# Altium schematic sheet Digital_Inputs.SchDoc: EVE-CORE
size A4; Organization: Ingenia Motion Control; Address1: Carrer Avila, 124, 2B; Address2: 08018 Barcelona Spain; Address3: www.ingeniamc.com; Address4: www.ingeniamc.com; Documentation: https://doc.ingeniamc.com/x/coAZBg
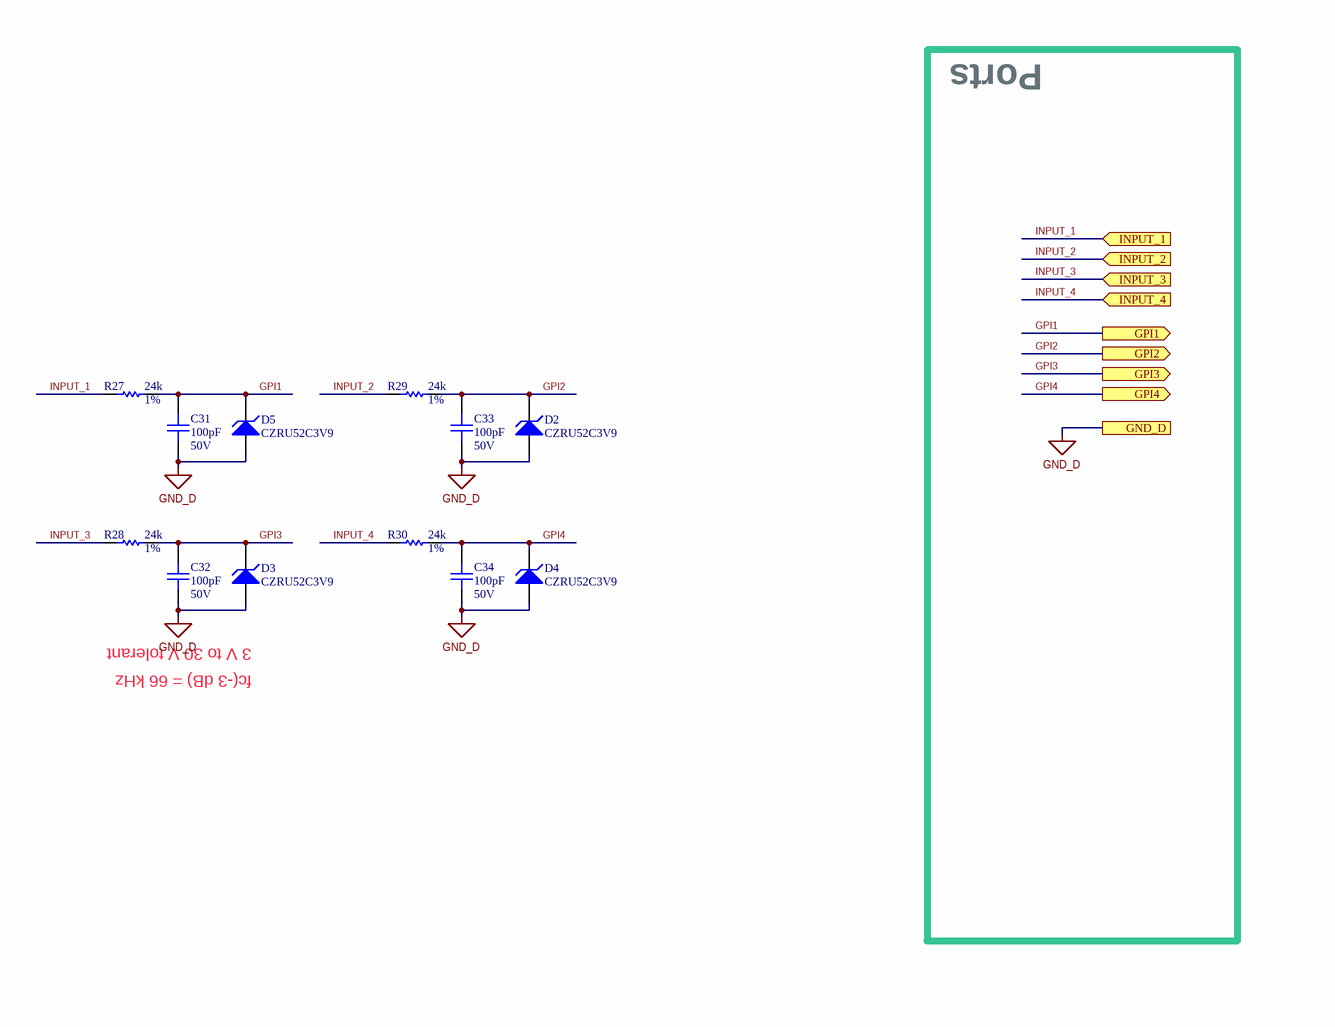
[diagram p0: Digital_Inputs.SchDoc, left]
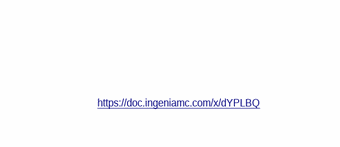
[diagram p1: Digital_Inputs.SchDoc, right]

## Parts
C31  value 100pF  Voltage: 50V  [C_0402]  (hidden comment: C_0402--100pF--50V)
C32  value 100pF  Voltage: 50V  [C_0402]  (hidden comment: C_0402--100pF--50V)
C33  value 100pF  Voltage: 50V  [C_0402]  (hidden comment: C_0402--100pF--50V)
C34  value 100pF  Voltage: 50V  [C_0402]  (hidden comment: C_0402--100pF--50V)
D2  CZRU52C3V9  [D_0603]
D3  CZRU52C3V9  [D_0603]
D4  CZRU52C3V9  [D_0603]
D5  CZRU52C3V9  [D_0603]
R27  value 24k  Tolerance: 1%  [R_0603]  (hidden comment: R_0603--24k--1%)
R28  value 24k  Tolerance: 1%  [R_0603]  (hidden comment: R_0603--24k--1%)
R29  value 24k  Tolerance: 1%  [R_0603]  (hidden comment: R_0603--24k--1%)
R30  value 24k  Tolerance: 1%  [R_0603]  (hidden comment: R_0603--24k--1%)

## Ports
GND_D, GPI1 (out), GPI2 (out), GPI3 (out), GPI4 (out), INPUT_1 (in), INPUT_2 (in), INPUT_3 (in), INPUT_4 (in)

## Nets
GND_D: C31.2 C32.2 C33.2 C34.2 D2.1(A) D3.1(A) D4.1(A) D5.1(A) ; port GND_D
GPI1: C31.1 D5.2(K) R27.2 ; port GPI1
GPI2: C33.1 D2.2(K) R29.2 ; port GPI2
GPI3: C32.1 D3.2(K) R28.2 ; port GPI3
GPI4: C34.1 D4.2(K) R30.2 ; port GPI4
INPUT_1: R27.1 ; port INPUT_1
INPUT_2: R29.1 ; port INPUT_2
INPUT_3: R28.1 ; port INPUT_3
INPUT_4: R30.1 ; port INPUT_4

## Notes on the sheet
- Ports
- 3 V to 30 V tolerant
- fc(-3 dB) = 66 kHz
- https://doc.ingeniamc.com/x/dYPLBQ

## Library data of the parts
C31-C34 = C_0402[[/\]]100pF[[/\]]50V: CAP CER 100pF 50V NP0/C0G 0402; ManufacturerName: Yageo; ManufacturerPN: CC0402JRNPO9BN101; AlternativeManufacturer: Kemet; IsPreferred: 0; IngeniaID: 1451; AdditionalInformation: NP0; AlternativePN: C0402H101J5GAFT1K0; MTBF55h: 77243743; TemperatureMaxC: 125; TemperatureMinC: -55
D2-D5 = CZRU52C3V9: DIODE ZENER 0.15W 5% 0603. 3.9 V @ 5mA, 3.3 V @ 1mA; ManufacturerName: Comchip; Value: 3.9V; IsPreferred: 0; IngeniaID: 4532
R27-R30 = R_0603[[/\]]24k[[/\]]1%: Resistor 1%; ManufacturerName: Yageo; ManufacturerPN: RC0603FR-0724KL; IsPreferred: 1; IngeniaID: 622; InternalStock: 0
